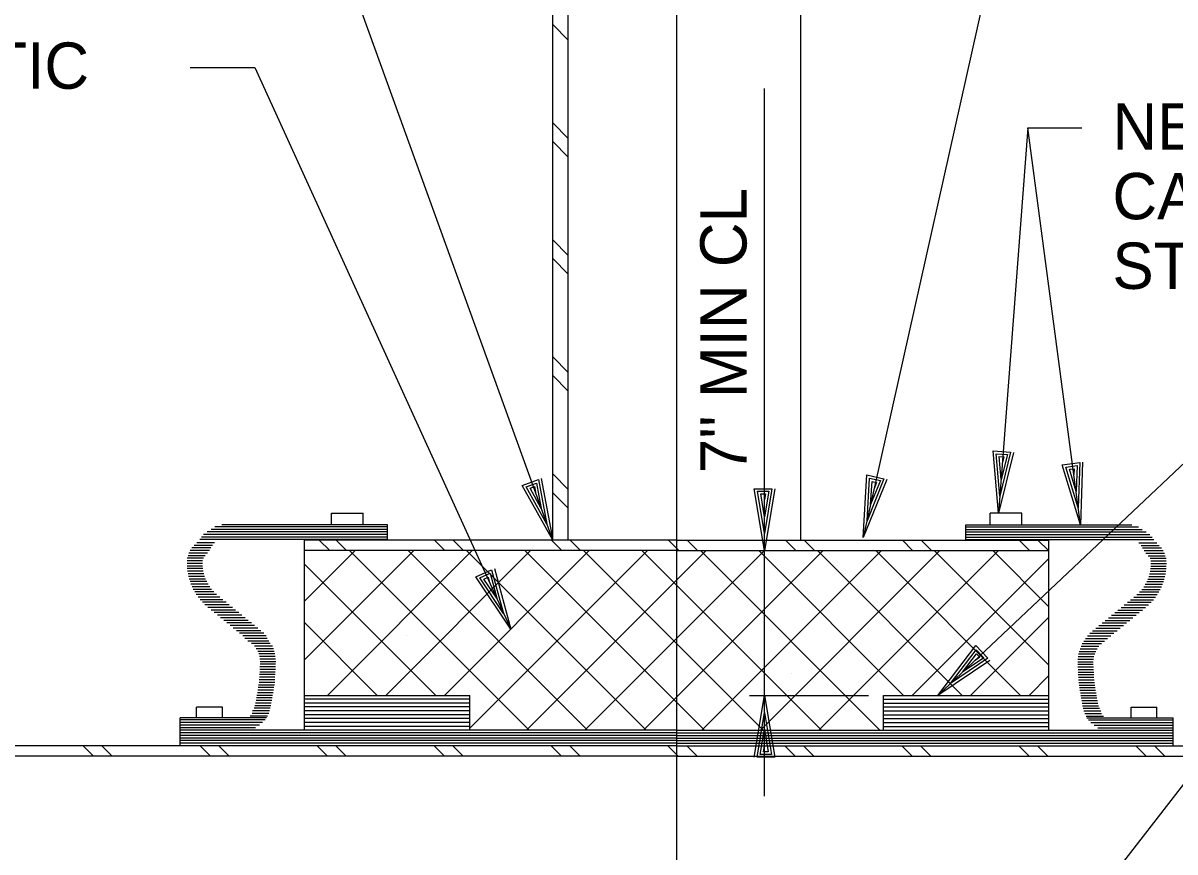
# Model space of a CAD drawing. Extents: x 22339.2 to 22413.4, y 22369.6 to 22418.8.
# Drawn here: x 22380.131 to 22384.774, y 22388.086 to 22391.426 of the extents above; entities that cross this region are included whole.
import ezdxf

# ---------------------------------------------------------------- set-up
doc = ezdxf.new("R2010")
doc.units = 0
for name, color, linetype in [('Level 1', 7, 'Continuous'), ('Level 2', 7, 'Continuous'), ('Level 4', 7, 'Continuous'), ('Level 8', 7, 'Continuous')]:
    doc.layers.add(name, color=color, linetype=linetype)

msp = doc.modelspace()

# ---------------------------------------------------------------- linework, layer by layer
at = {"layer": 'Level 1'}
for p, q in [((22382.7659, 22384.5979), (22382.7659, 22394.0328)), ((22383.1197, 22389.3005), (22383.1197, 22391.1625)), ((22384.3669, 22389.6069), (22384.3669, 22389.6069)), ((22382.2424, 22389.5324), (22382.2424, 22389.5324)), ((22384.3755, 22389.5424), (22384.3755, 22389.5424)), ((22384.376, 22389.5381), (22384.376, 22389.5381)), ((22384.376, 22389.5381), (22384.376, 22389.5381)), ((22381.3747, 22389.4038), (22381.3747, 22389.4515)), ((22381.3747, 22389.4515), (22381.5022, 22389.4515)), ((22381.5022, 22389.4038), (22381.5022, 22389.4515)), ((22382.2659, 22389.4672), (22382.2659, 22389.4672)), ((22384.0297, 22389.4038), (22384.0297, 22389.4515)), ((22384.1572, 22389.4515), (22384.0297, 22389.4515)), ((22384.1572, 22389.4038), (22384.1572, 22389.4515)), ((22381.2659, 22388.5765), (22381.2659, 22389.3422)), ((22382.7659, 22389.3422), (22381.2659, 22389.3422)), ((22382.7659, 22389.3422), (22384.2659, 22389.3422)), ((22384.2659, 22388.5765), (22384.2659, 22389.3422)), ((22382.7659, 22389.3005), (22381.2659, 22389.3005)), ((22382.7659, 22389.3005), (22384.2659, 22389.3005)), ((22383.1197, 22388.7172), (22383.1197, 22389.3005)), ((22381.6351, 22389.0152), (22381.6351, 22389.0152)), ((22381.6763, 22388.9594), (22381.6763, 22388.9594)), ((22383.2276, 22388.8065), (22383.2276, 22388.8065)), ((22383.2171, 22388.738), (22383.2171, 22388.738)), ((22381.9326, 22388.7015), (22381.2659, 22388.7015)), ((22381.9326, 22388.6859), (22381.2659, 22388.6859)), ((22383.0589, 22388.7172), (22383.5394, 22388.7172)), ((22383.1197, 22388.3111), (22383.1197, 22388.7172)), ((22383.5993, 22388.7015), (22384.2659, 22388.7015)), ((22383.5993, 22388.6859), (22384.2659, 22388.6859)), ((22380.8307, 22388.6262), (22380.8307, 22388.6692)), ((22380.9344, 22388.6692), (22380.8307, 22388.6692)), ((22380.9344, 22388.6262), (22380.9344, 22388.6692)), ((22381.9326, 22388.6703), (22381.2659, 22388.6703)), ((22381.9326, 22388.6547), (22381.2659, 22388.6547)), ((22381.9326, 22388.639), (22381.2659, 22388.639)), ((22383.5993, 22388.6703), (22384.2659, 22388.6703)), ((22383.5993, 22388.6547), (22384.2659, 22388.6547)), ((22383.5993, 22388.639), (22384.2659, 22388.639)), ((22384.5975, 22388.6262), (22384.5975, 22388.6692)), ((22384.5975, 22388.6692), (22384.7012, 22388.6692)), ((22384.7012, 22388.6262), (22384.7012, 22388.6692)), ((22381.9326, 22388.6234), (22381.2659, 22388.6234)), ((22381.9326, 22388.6078), (22381.2659, 22388.6078)), ((22381.9326, 22388.5922), (22381.2659, 22388.5922)), ((22383.5993, 22388.6234), (22384.2659, 22388.6234)), ((22383.5993, 22388.6078), (22384.2659, 22388.6078)), ((22383.5993, 22388.5922), (22384.2659, 22388.5922))]:
    msp.add_line(p, q, dxfattribs=at)
msp.add_lwpolyline([(22384.3765, 22389.5539), (22384.376, 22389.5381), (22384.3714, 22389.5532), (22384.3758, 22389.5538), (22384.3755, 22389.5424), (22384.3723, 22389.5527), (22384.3751, 22389.5531), (22384.3749, 22389.5466), (22384.3732, 22389.5521), (22384.3744, 22389.5523), (22384.3743, 22389.5508)], dxfattribs=at)
at = {"layer": 'Level 2'}
for p, q in [((22382.2659, 22389.3422), (22382.2659, 22393.2738)), ((22382.3284, 22389.3422), (22382.3284, 22393.2738)), ((22383.2659, 22389.3422), (22383.2659, 22393.2738)), ((22382.2659, 22389.3422), (22381.3162, 22391.9696)), ((22384.3938, 22389.4038), (22384.1818, 22391.0035)), ((22384.1818, 22391.0035), (22384.3994, 22391.0035)), ((22381.6005, 22389.4038), (22380.932, 22389.4038)), ((22381.6005, 22389.3422), (22381.6005, 22389.4038)), ((22383.9314, 22389.4038), (22384.6009, 22389.4038)), ((22383.9314, 22389.3422), (22383.9314, 22389.4038)), ((22385.4904, 22389.2365), (22384.3699, 22387.7953)), ((22381.2659, 22388.5765), (22381.2659, 22388.7172)), ((22381.2659, 22388.7172), (22381.9326, 22388.7172)), ((22381.9326, 22388.5765), (22381.9326, 22388.7172)), ((22383.5993, 22388.5765), (22383.5993, 22388.7172)), ((22383.5993, 22388.7172), (22384.2659, 22388.7172)), ((22384.2659, 22388.5765), (22384.2659, 22388.7172)), ((22380.7647, 22388.514), (22380.7647, 22388.6262)), ((22381.1127, 22388.6262), (22380.7647, 22388.6262)), ((22384.4192, 22388.6262), (22384.7672, 22388.6262)), ((22384.7672, 22388.514), (22384.7672, 22388.6262)), ((22382.7659, 22388.5765), (22380.7647, 22388.5765)), ((22382.7659, 22388.5661), (22380.7647, 22388.5661)), ((22382.7659, 22388.5557), (22380.7647, 22388.5557)), ((22382.7659, 22388.5453), (22380.7647, 22388.5453)), ((22382.7659, 22388.5765), (22384.7672, 22388.5765)), ((22382.7659, 22388.5661), (22384.7672, 22388.5661)), ((22382.7659, 22388.5557), (22384.7672, 22388.5557)), ((22382.7659, 22388.5453), (22384.7672, 22388.5453)), ((22382.7659, 22388.514), (22376.0992, 22388.514)), ((22382.7659, 22388.5349), (22380.7647, 22388.5349)), ((22382.7659, 22388.5244), (22380.7647, 22388.5244)), ((22382.7659, 22388.5349), (22384.7672, 22388.5349)), ((22382.7659, 22388.5244), (22384.7672, 22388.5244)), ((22382.7659, 22388.514), (22389.4102, 22388.514)), ((22382.7659, 22388.4724), (22376.1285, 22388.4724)), ((22382.7659, 22388.4724), (22389.4006, 22388.4724))]:
    msp.add_line(p, q, dxfattribs=at)
for points in [[(22384.3907, 22391.9303), (22384.0942, 22391.9303), (22383.518, 22389.353)], [(22380.8047, 22391.2463), (22381.0652, 22391.2463), (22382.0967, 22388.9844)], [(22384.1818, 22391.0035), (22384.0635, 22389.4506)], [(22385.2561, 22389.8368), (22385.0094, 22389.8386), (22383.8188, 22388.7172)], [(22384.1237, 22389.6961), (22384.0635, 22389.4506), (22384.0412, 22389.7024), (22384.1117, 22389.697), (22384.0688, 22389.5197), (22384.0537, 22389.6907), (22384.0989, 22389.6873), (22384.0739, 22389.5862), (22384.0662, 22389.6791), (22384.0848, 22389.6776), (22384.0791, 22389.6553)], [(22384.402, 22389.6564), (22384.3938, 22389.4038), (22384.3201, 22389.6455), (22384.3902, 22389.6548), (22384.3847, 22389.4725), (22384.3347, 22389.6367), (22384.3797, 22389.6427), (22384.376, 22389.5386), (22384.3493, 22389.6279), (22384.3678, 22389.6304), (22384.3669, 22389.6074)], [(22382.2201, 22389.5907), (22382.2659, 22389.3422), (22382.1423, 22389.5626), (22382.2088, 22389.5866), (22382.2424, 22389.4074), (22382.1585, 22389.5571), (22382.2011, 22389.5725), (22382.2197, 22389.4701), (22382.1746, 22389.5516), (22382.1922, 22389.5579), (22382.1961, 22389.5353)], [(22383.6127, 22389.5873), (22383.518, 22389.353), (22383.5321, 22389.6053), (22383.601, 22389.5899), (22383.5331, 22389.4207), (22383.5427, 22389.592), (22383.587, 22389.5821), (22383.5477, 22389.4857), (22383.5534, 22389.5787), (22383.5717, 22389.5746), (22383.5628, 22389.5534)], [(22383.161, 22389.5498), (22383.1197, 22389.3005), (22383.0784, 22389.5498), (22383.149, 22389.5498), (22383.1197, 22389.3698), (22383.0917, 22389.5392), (22383.137, 22389.5392), (22383.1197, 22389.4365), (22383.105, 22389.5285), (22383.1237, 22389.5285), (22383.1197, 22389.5058)], [(22381.5993, 22389.386), (22380.8895, 22389.386)], [(22381.5993, 22389.3964), (22380.9047, 22389.3964)], [(22383.9326, 22389.3964), (22384.6272, 22389.3964)], [(22383.9326, 22389.386), (22384.6424, 22389.386)], [(22381.5993, 22389.3444), (22380.8434, 22389.3444)], [(22381.5993, 22389.3548), (22380.8499, 22389.3548)], [(22381.5993, 22389.3652), (22380.8584, 22389.3652)], [(22381.5993, 22389.3756), (22380.8736, 22389.3756)], [(22383.9326, 22389.3756), (22384.6582, 22389.3756)], [(22383.9326, 22389.3652), (22384.6735, 22389.3652)], [(22383.9326, 22389.3548), (22384.682, 22389.3548)], [(22383.9326, 22389.3444), (22384.6885, 22389.3444)], [(22380.875, 22389.2901), (22380.7995, 22389.2901)], [(22380.8821, 22389.3005), (22380.8053, 22389.3005)], [(22380.8885, 22389.3109), (22380.8118, 22389.3109)], [(22380.8944, 22389.3213), (22380.8208, 22389.3213)], [(22380.9034, 22389.3317), (22380.8311, 22389.3317)], [(22384.6285, 22389.3317), (22384.7007, 22389.3317)], [(22384.6375, 22389.3213), (22384.7111, 22389.3213)], [(22384.6433, 22389.3109), (22384.7201, 22389.3109)], [(22384.6498, 22389.3005), (22384.7265, 22389.3005)], [(22384.6569, 22389.2901), (22384.7324, 22389.2901)], [(22380.8547, 22389.2484), (22380.7922, 22389.2484)], [(22380.855, 22389.2588), (22380.7924, 22389.2588)], [(22380.8582, 22389.2692), (22380.7931, 22389.2692)], [(22380.8653, 22389.2797), (22380.797, 22389.2797)], [(22384.6666, 22389.2797), (22384.7349, 22389.2797)], [(22384.6737, 22389.2692), (22384.7388, 22389.2692)], [(22384.6769, 22389.2588), (22384.7395, 22389.2588)], [(22384.6772, 22389.2484), (22384.7397, 22389.2484)], [(22380.855, 22389.238), (22380.7924, 22389.238)], [(22380.856, 22389.2276), (22380.7931, 22389.2276)], [(22380.8577, 22389.2172), (22380.7943, 22389.2172)], [(22380.86, 22389.2067), (22380.796, 22389.2067)], [(22380.8631, 22389.1963), (22380.7982, 22389.1963)], [(22382.0309, 22389.2284), (22382.0967, 22388.9844), (22381.9557, 22389.1941), (22382.02, 22389.2235), (22382.068, 22389.0475), (22381.9722, 22389.19), (22382.0135, 22389.2088), (22382.0403, 22389.1082), (22381.9888, 22389.1858), (22382.0058, 22389.1935), (22382.0115, 22389.1713)], [(22384.6688, 22389.1963), (22384.7337, 22389.1963)], [(22384.6719, 22389.2067), (22384.7359, 22389.2067)], [(22384.6742, 22389.2172), (22384.7376, 22389.2172)], [(22384.6759, 22389.2276), (22384.7387, 22389.2276)], [(22384.6769, 22389.238), (22384.7395, 22389.238)], [(22380.8669, 22389.1859), (22380.8009, 22389.1859)], [(22380.8715, 22389.1755), (22380.8041, 22389.1755)], [(22380.8771, 22389.1651), (22380.8079, 22389.1651)], [(22380.8836, 22389.1547), (22380.8123, 22389.1547)], [(22384.6483, 22389.1547), (22384.7196, 22389.1547)], [(22384.6548, 22389.1651), (22384.724, 22389.1651)], [(22384.6604, 22389.1755), (22384.7278, 22389.1755)], [(22384.665, 22389.1859), (22384.731, 22389.1859)], [(22380.8913, 22389.1442), (22380.8173, 22389.1442)], [(22380.9004, 22389.1338), (22380.8229, 22389.1338)], [(22380.9112, 22389.1234), (22380.8293, 22389.1234)], [(22380.9238, 22389.113), (22380.8365, 22389.113)], [(22380.9365, 22389.1026), (22380.8447, 22389.1026)], [(22384.5953, 22389.1026), (22384.6872, 22389.1026)], [(22384.6081, 22389.113), (22384.6953, 22389.113)], [(22384.6207, 22389.1234), (22384.7026, 22389.1234)], [(22384.6315, 22389.1338), (22384.709, 22389.1338)], [(22384.6406, 22389.1442), (22384.7146, 22389.1442)], [(22380.9493, 22389.0922), (22380.8538, 22389.0922)], [(22380.9621, 22389.0817), (22380.8642, 22389.0817)], [(22380.9749, 22389.0713), (22380.876, 22389.0713)], [(22380.9876, 22389.0609), (22380.8888, 22389.0609)], [(22384.5443, 22389.0609), (22384.6431, 22389.0609)], [(22384.557, 22389.0713), (22384.6559, 22389.0713)], [(22384.5698, 22389.0817), (22384.6677, 22389.0817)], [(22384.5826, 22389.0922), (22384.6781, 22389.0922)], [(22381.0004, 22389.0505), (22380.9015, 22389.0505)], [(22381.0132, 22389.0401), (22380.9143, 22389.0401)], [(22381.0259, 22389.0297), (22380.9271, 22389.0297)], [(22381.0387, 22389.0192), (22380.9398, 22389.0192)], [(22381.0515, 22389.0088), (22380.9526, 22389.0088)], [(22384.4804, 22389.0088), (22384.5793, 22389.0088)], [(22384.4932, 22389.0192), (22384.5921, 22389.0192)], [(22384.506, 22389.0297), (22384.6048, 22389.0297)], [(22384.5187, 22389.0401), (22384.6176, 22389.0401)], [(22384.5315, 22389.0505), (22384.6304, 22389.0505)], [(22381.0642, 22388.9984), (22380.9654, 22388.9984)], [(22381.077, 22388.988), (22380.9781, 22388.988)], [(22381.0897, 22388.9776), (22380.9909, 22388.9776)], [(22381.1011, 22388.9672), (22381.0037, 22388.9672)], [(22384.4308, 22388.9672), (22384.5282, 22388.9672)], [(22384.4422, 22388.9776), (22384.541, 22388.9776)], [(22384.4549, 22388.988), (22384.5538, 22388.988)], [(22384.4677, 22388.9984), (22384.5665, 22388.9984)], [(22381.1105, 22388.9567), (22381.0164, 22388.9567)], [(22381.1147, 22388.9463), (22381.0253, 22388.9463)], [(22381.1218, 22388.9359), (22381.0366, 22388.9359)], [(22381.1275, 22388.9255), (22381.0522, 22388.9255)], [(22381.1361, 22388.9151), (22381.0639, 22388.9151)], [(22384.0287, 22388.858), (22383.8188, 22388.7172), (22383.972, 22388.9182), (22384.0204, 22388.8668), (22383.8693, 22388.7647), (22383.9734, 22388.9012), (22384.0044, 22388.8682), (22383.9178, 22388.8104), (22383.9747, 22388.8842), (22383.9875, 22388.8706), (22383.9683, 22388.8579)], [(22384.3958, 22388.9151), (22384.468, 22388.9151)], [(22384.4007, 22388.9255), (22384.4776, 22388.9255)], [(22384.4065, 22388.9359), (22384.4899, 22388.9359)], [(22384.4133, 22388.9463), (22384.5027, 22388.9463)], [(22384.4213, 22388.9567), (22384.5155, 22388.9567)], [(22381.1401, 22388.9047), (22381.0713, 22388.9047)], [(22381.1434, 22388.8942), (22381.077, 22388.8942)], [(22381.1459, 22388.8838), (22381.0812, 22388.8838)], [(22381.1477, 22388.8734), (22381.0842, 22388.8734)], [(22384.3841, 22388.8734), (22384.4477, 22388.8734)], [(22384.386, 22388.8838), (22384.4507, 22388.8838)], [(22384.3885, 22388.8942), (22384.4549, 22388.8942)], [(22384.3918, 22388.9047), (22384.4606, 22388.9047)], [(22381.1485, 22388.8317), (22381.0854, 22388.8317)], [(22381.1489, 22388.863), (22381.0861, 22388.863)], [(22381.1493, 22388.8422), (22381.0867, 22388.8422)], [(22381.1494, 22388.8526), (22381.0869, 22388.8526)], [(22384.3825, 22388.8526), (22384.445, 22388.8526)], [(22384.3826, 22388.8422), (22384.4452, 22388.8422)], [(22384.383, 22388.863), (22384.4458, 22388.863)], [(22384.3834, 22388.8317), (22384.4465, 22388.8317)], [(22381.146, 22388.7797), (22381.0833, 22388.7797)], [(22381.1465, 22388.7901), (22381.084, 22388.7901)], [(22381.1471, 22388.8005), (22381.0845, 22388.8005)], [(22381.1477, 22388.8109), (22381.0851, 22388.8109)], [(22381.1483, 22388.8213), (22381.0857, 22388.8213)], [(22384.3836, 22388.8213), (22384.4462, 22388.8213)], [(22384.3842, 22388.8109), (22384.4468, 22388.8109)], [(22384.3848, 22388.8005), (22384.4474, 22388.8005)], [(22384.3853, 22388.7901), (22384.4479, 22388.7901)], [(22384.3859, 22388.7797), (22384.4486, 22388.7797)], [(22381.1408, 22388.738), (22381.0773, 22388.738)], [(22381.1425, 22388.7484), (22381.0791, 22388.7484)], [(22381.1441, 22388.7588), (22381.0808, 22388.7588)], [(22381.1453, 22388.7692), (22381.0823, 22388.7692)], [(22384.3866, 22388.7692), (22384.4496, 22388.7692)], [(22384.3878, 22388.7588), (22384.4511, 22388.7588)], [(22384.3894, 22388.7484), (22384.4527, 22388.7484)], [(22384.3911, 22388.738), (22384.4546, 22388.738)], [(22381.1318, 22388.6859), (22381.068, 22388.6859)], [(22381.1336, 22388.6963), (22381.0702, 22388.6963)], [(22381.1354, 22388.7067), (22381.0719, 22388.7067)], [(22381.1371, 22388.7172), (22381.0737, 22388.7172)], [(22381.139, 22388.7276), (22381.0755, 22388.7276)], [(22383.0784, 22388.4678), (22383.1197, 22388.7172), (22383.161, 22388.4678), (22383.0904, 22388.4678), (22383.1197, 22388.6478), (22383.1477, 22388.4785), (22383.1024, 22388.4785), (22383.1197, 22388.5812), (22383.1344, 22388.4892), (22383.1157, 22388.4892), (22383.1197, 22388.5118)], [(22384.3929, 22388.7276), (22384.4564, 22388.7276)], [(22384.3948, 22388.7172), (22384.4582, 22388.7172)], [(22384.3965, 22388.7067), (22384.46, 22388.7067)], [(22384.3983, 22388.6963), (22384.4617, 22388.6963)], [(22384.4001, 22388.6859), (22384.4639, 22388.6859)], [(22381.1212, 22388.6442), (22381.0543, 22388.6442)], [(22381.1246, 22388.6547), (22381.0559, 22388.6547)], [(22381.1274, 22388.6651), (22381.0622, 22388.6651)], [(22381.1298, 22388.6755), (22381.0654, 22388.6755)], [(22384.4021, 22388.6755), (22384.4665, 22388.6755)], [(22384.4045, 22388.6651), (22384.4697, 22388.6651)], [(22384.4073, 22388.6547), (22384.476, 22388.6547)], [(22384.4107, 22388.6442), (22384.4776, 22388.6442)], [(22381.1064, 22388.6182), (22380.7659, 22388.6182)], [(22381.0962, 22388.6078), (22380.7659, 22388.6078)], [(22381.0838, 22388.5974), (22380.7659, 22388.5974)], [(22381.1159, 22388.6338), (22381.0462, 22388.6338)], [(22384.4159, 22388.6338), (22384.4857, 22388.6338)], [(22384.4255, 22388.6182), (22384.7659, 22388.6182)], [(22384.4357, 22388.6078), (22384.7659, 22388.6078)], [(22384.4481, 22388.5974), (22384.7659, 22388.5974)], [(22381.0479, 22388.5765), (22380.7647, 22388.5765)], [(22381.0684, 22388.5869), (22380.7659, 22388.5869)], [(22384.4635, 22388.5869), (22384.7659, 22388.5869)], [(22384.484, 22388.5765), (22384.7672, 22388.5765)]]:
    msp.add_lwpolyline(points, dxfattribs=at)
at = {"layer": 'Level 8'}
for p, q in [((22384.0688, 22389.5197), (22384.0688, 22389.5197)), ((22384.0635, 22389.4506), (22384.0635, 22389.4506)), ((22383.5331, 22389.4207), (22383.5331, 22389.4207)), ((22383.1197, 22389.3698), (22383.1197, 22389.3698)), ((22383.518, 22389.353), (22383.518, 22389.353)), ((22383.1197, 22389.3005), (22383.1197, 22389.3005)), ((22382.068, 22389.0475), (22382.068, 22389.0475)), ((22382.0967, 22388.9844), (22382.0967, 22388.9844)), ((22383.8693, 22388.7647), (22383.8693, 22388.7647)), ((22383.1197, 22388.7172), (22383.1197, 22388.7172)), ((22383.8188, 22388.7172), (22383.8188, 22388.7172)), ((22383.1197, 22388.6478), (22383.1197, 22388.6478))]:
    msp.add_line(p, q, dxfattribs=at)
for points in [[(22382.3284, 22391.3567), (22382.2659, 22391.4193)], [(22382.3284, 22390.9608), (22382.2659, 22391.0233)], [(22382.3284, 22390.8853), (22382.2659, 22390.9479)], [(22382.3284, 22390.4894), (22382.2659, 22390.5519)], [(22382.3284, 22390.4139), (22382.2659, 22390.4765)], [(22382.3284, 22390.018), (22382.2659, 22390.0805)], [(22382.3284, 22389.9425), (22382.2659, 22390.0051)], [(22382.3284, 22389.5466), (22382.2659, 22389.6091)], [(22382.3284, 22389.4711), (22382.2659, 22389.5336)], [(22381.367, 22389.3005), (22381.3253, 22389.3422)], [(22381.4355, 22389.3005), (22381.3938, 22389.3422)], [(22381.8314, 22389.3005), (22381.7898, 22389.3422)], [(22381.9069, 22389.3005), (22381.8652, 22389.3422)], [(22382.3028, 22389.3005), (22382.2612, 22389.3422)], [(22382.3783, 22389.3005), (22382.3366, 22389.3422)], [(22382.7743, 22389.3005), (22382.7326, 22389.3422)], [(22382.8497, 22389.3005), (22382.808, 22389.3422)], [(22383.2457, 22389.3005), (22383.204, 22389.3422)], [(22383.3211, 22389.3005), (22383.2794, 22389.3422)], [(22383.717, 22389.3005), (22383.6754, 22389.3422)], [(22383.7925, 22389.3005), (22383.7508, 22389.3422)], [(22384.1885, 22389.3005), (22384.1468, 22389.3422)], [(22384.2639, 22389.3005), (22384.2222, 22389.3422)], [(22381.2659, 22388.8607), (22381.7057, 22389.3005)], [(22381.2659, 22389.0964), (22381.47, 22389.3005)], [(22381.3581, 22388.7172), (22381.9414, 22389.3005)], [(22382.1711, 22388.5765), (22381.4471, 22389.3005)], [(22381.5938, 22388.7172), (22382.1771, 22389.3005)], [(22382.4068, 22388.5765), (22381.6828, 22389.3005)], [(22381.8295, 22388.7172), (22382.4128, 22389.3005)], [(22382.6425, 22388.5765), (22381.9185, 22389.3005)], [(22381.9326, 22388.5846), (22382.6485, 22389.3005)], [(22382.8782, 22388.5765), (22382.1542, 22389.3005)], [(22382.1602, 22388.5765), (22382.8842, 22389.3005)], [(22383.1139, 22388.5765), (22382.3899, 22389.3005)], [(22382.3959, 22388.5765), (22383.1199, 22389.3005)], [(22383.3496, 22388.5765), (22382.6257, 22389.3005)], [(22382.6316, 22388.5765), (22383.3556, 22389.3005)], [(22383.5853, 22388.5765), (22382.8614, 22389.3005)], [(22382.8674, 22388.5765), (22383.5913, 22389.3005)], [(22383.6804, 22388.7172), (22383.0971, 22389.3005)], [(22383.103, 22388.5765), (22383.827, 22389.3005)], [(22383.9161, 22388.7172), (22383.3328, 22389.3005)], [(22383.3388, 22388.5765), (22384.0627, 22389.3005)], [(22384.1518, 22388.7172), (22383.5685, 22389.3005)], [(22384.2659, 22388.8387), (22383.8042, 22389.3005)], [(22384.2659, 22389.0744), (22384.0399, 22389.3005)], [(22381.7948, 22388.7172), (22381.266, 22389.246)], [(22383.7151, 22388.7172), (22384.2659, 22389.268)], [(22381.5591, 22388.7172), (22381.266, 22389.0103)], [(22383.9508, 22388.7172), (22384.2659, 22389.0323)], [(22384.1865, 22388.7172), (22384.2659, 22388.7966)], [(22380.4153, 22388.4724), (22380.3736, 22388.514)], [(22380.4907, 22388.4724), (22380.4491, 22388.514)], [(22380.8867, 22388.4724), (22380.845, 22388.514)], [(22380.9621, 22388.4724), (22380.9205, 22388.514)], [(22381.3581, 22388.4724), (22381.3164, 22388.514)], [(22381.4335, 22388.4724), (22381.3919, 22388.514)], [(22381.8295, 22388.4724), (22381.7879, 22388.514)], [(22381.9049, 22388.4724), (22381.8633, 22388.514)], [(22382.3009, 22388.4724), (22382.2593, 22388.514)], [(22382.3764, 22388.4724), (22382.3347, 22388.514)], [(22382.7723, 22388.4724), (22382.7307, 22388.514)], [(22382.8477, 22388.4724), (22382.8061, 22388.514)], [(22383.2437, 22388.4724), (22383.2021, 22388.514)], [(22383.3192, 22388.4724), (22383.2775, 22388.514)], [(22383.7151, 22388.4724), (22383.6735, 22388.514)], [(22383.7906, 22388.4724), (22383.7489, 22388.514)], [(22384.1865, 22388.4724), (22384.1449, 22388.514)], [(22384.262, 22388.4724), (22384.2203, 22388.514)], [(22384.6579, 22388.4724), (22384.6163, 22388.514)], [(22384.7334, 22388.4724), (22384.6917, 22388.514)]]:
    msp.add_lwpolyline(points, dxfattribs=at)

# ---------------------------------------------------------------- texts
at = {"layer": 'Level 4'}
for s, p in [('PACK WITH PLASTIC', (22377.9007, 22391.1608)), ('NEOPRENE RUBBER SLEEVE TYPE', (22384.5223, 22390.9156)), ('CASING SEAL WITH STAINLESS', (22384.5223, 22390.6351)), ('STEEL BANDS AND CLAMPS', (22384.5223, 22390.3547))]:
    msp.add_text(s, height=0.186667, dxfattribs=at).set_placement(p)
msp.add_text("7'' MIN CL ", height=0.186667, rotation=90, dxfattribs=at).set_placement((22383.0474, 22389.6117))

doc.saveas('drawing.dxf')
